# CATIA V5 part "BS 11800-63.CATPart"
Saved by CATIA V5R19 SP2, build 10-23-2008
Part number: BS 11800-63
Bounding box of the stored display mesh (mm): x -74.81 to 74.81, y -74.81 to 74.81, z 0 to 204
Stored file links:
  C:\Users\Bora\Desktop\3D Katı model\BS serisi\BS 11800\BS 11800-63.CATPart
  C:\Program Files\Dassault Systemes\B19\intel_a\reffiles\standard\MetricThickPitch.txt
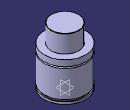
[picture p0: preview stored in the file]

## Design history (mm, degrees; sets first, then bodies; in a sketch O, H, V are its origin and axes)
Body1 (main body)
  Sketch1 on yz-plane, origin (0, 0, 0), H (0, 1, 0), V (0, 0, 1)
    point P1 (75, 118)
    point P2 (75, 113)
    point P5 (50, 203)
    point P7 (50, 203)
    point P12 (75, 113)
    point P13 (75, 118)
    arc A1 centre (75, 115.5) radius 2.5 from (75, 118) to (75, 113) ccw
    line L1 (75, 0) -> (75, 8)
    line L2 (50, 203) -> (50, 140)
    arc A2 centre (49, 203) radius 1 from (50, 203) to (49, 204) ccw
    line L3 (71, 15) -> (71, 8)
    line L4 (75, 15) -> (75, 113)
    line L5 (75, 118) -> (75, 140)
    line L6 (49, 204) -> (0, 204)
    point P15 (0, 204)
    line L7 (50, 140) -> (75, 140)
    line L8 (0, 0) -> (75, 0)
    line L9 (71, 15) -> (75, 15)
    line L10 (71, 8) -> (75, 8)
    coincidence: P15 V, P1 P13, P2 P12, P5 P7
    tangency: L6 A2
    horizontal: L7 H, L8 H, L9 H, L10 H
  Shaft1: profile Sketch1, axis Sketch1.V, angle 360
  Sketch2 on face of Shaft1 from Sketch1.L8, origin (0, 0, 0), H (1, 0, 0), V (0, -1, 0)
    point P1 (50, 0)
    distance P1 V = 50
  Hole1: placed by Sketch2, at (50, 0, 0) direction (0, 0, 1), diameter 8.376, depth 12, threaded "M10", thread diameter 10, thread depth 12, pitch 1.5
  CircPattern1: of Hole1, instances 4, angular step 90, axis from xy-plane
